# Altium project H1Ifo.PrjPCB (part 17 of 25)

## Sheet IfoEndX1.SchDoc: D1800185
size C; Engineer: Daniel Sigg; DocumentNumber: 5; Revision: 4; SheetNumber: 5; SheetTotal: 8
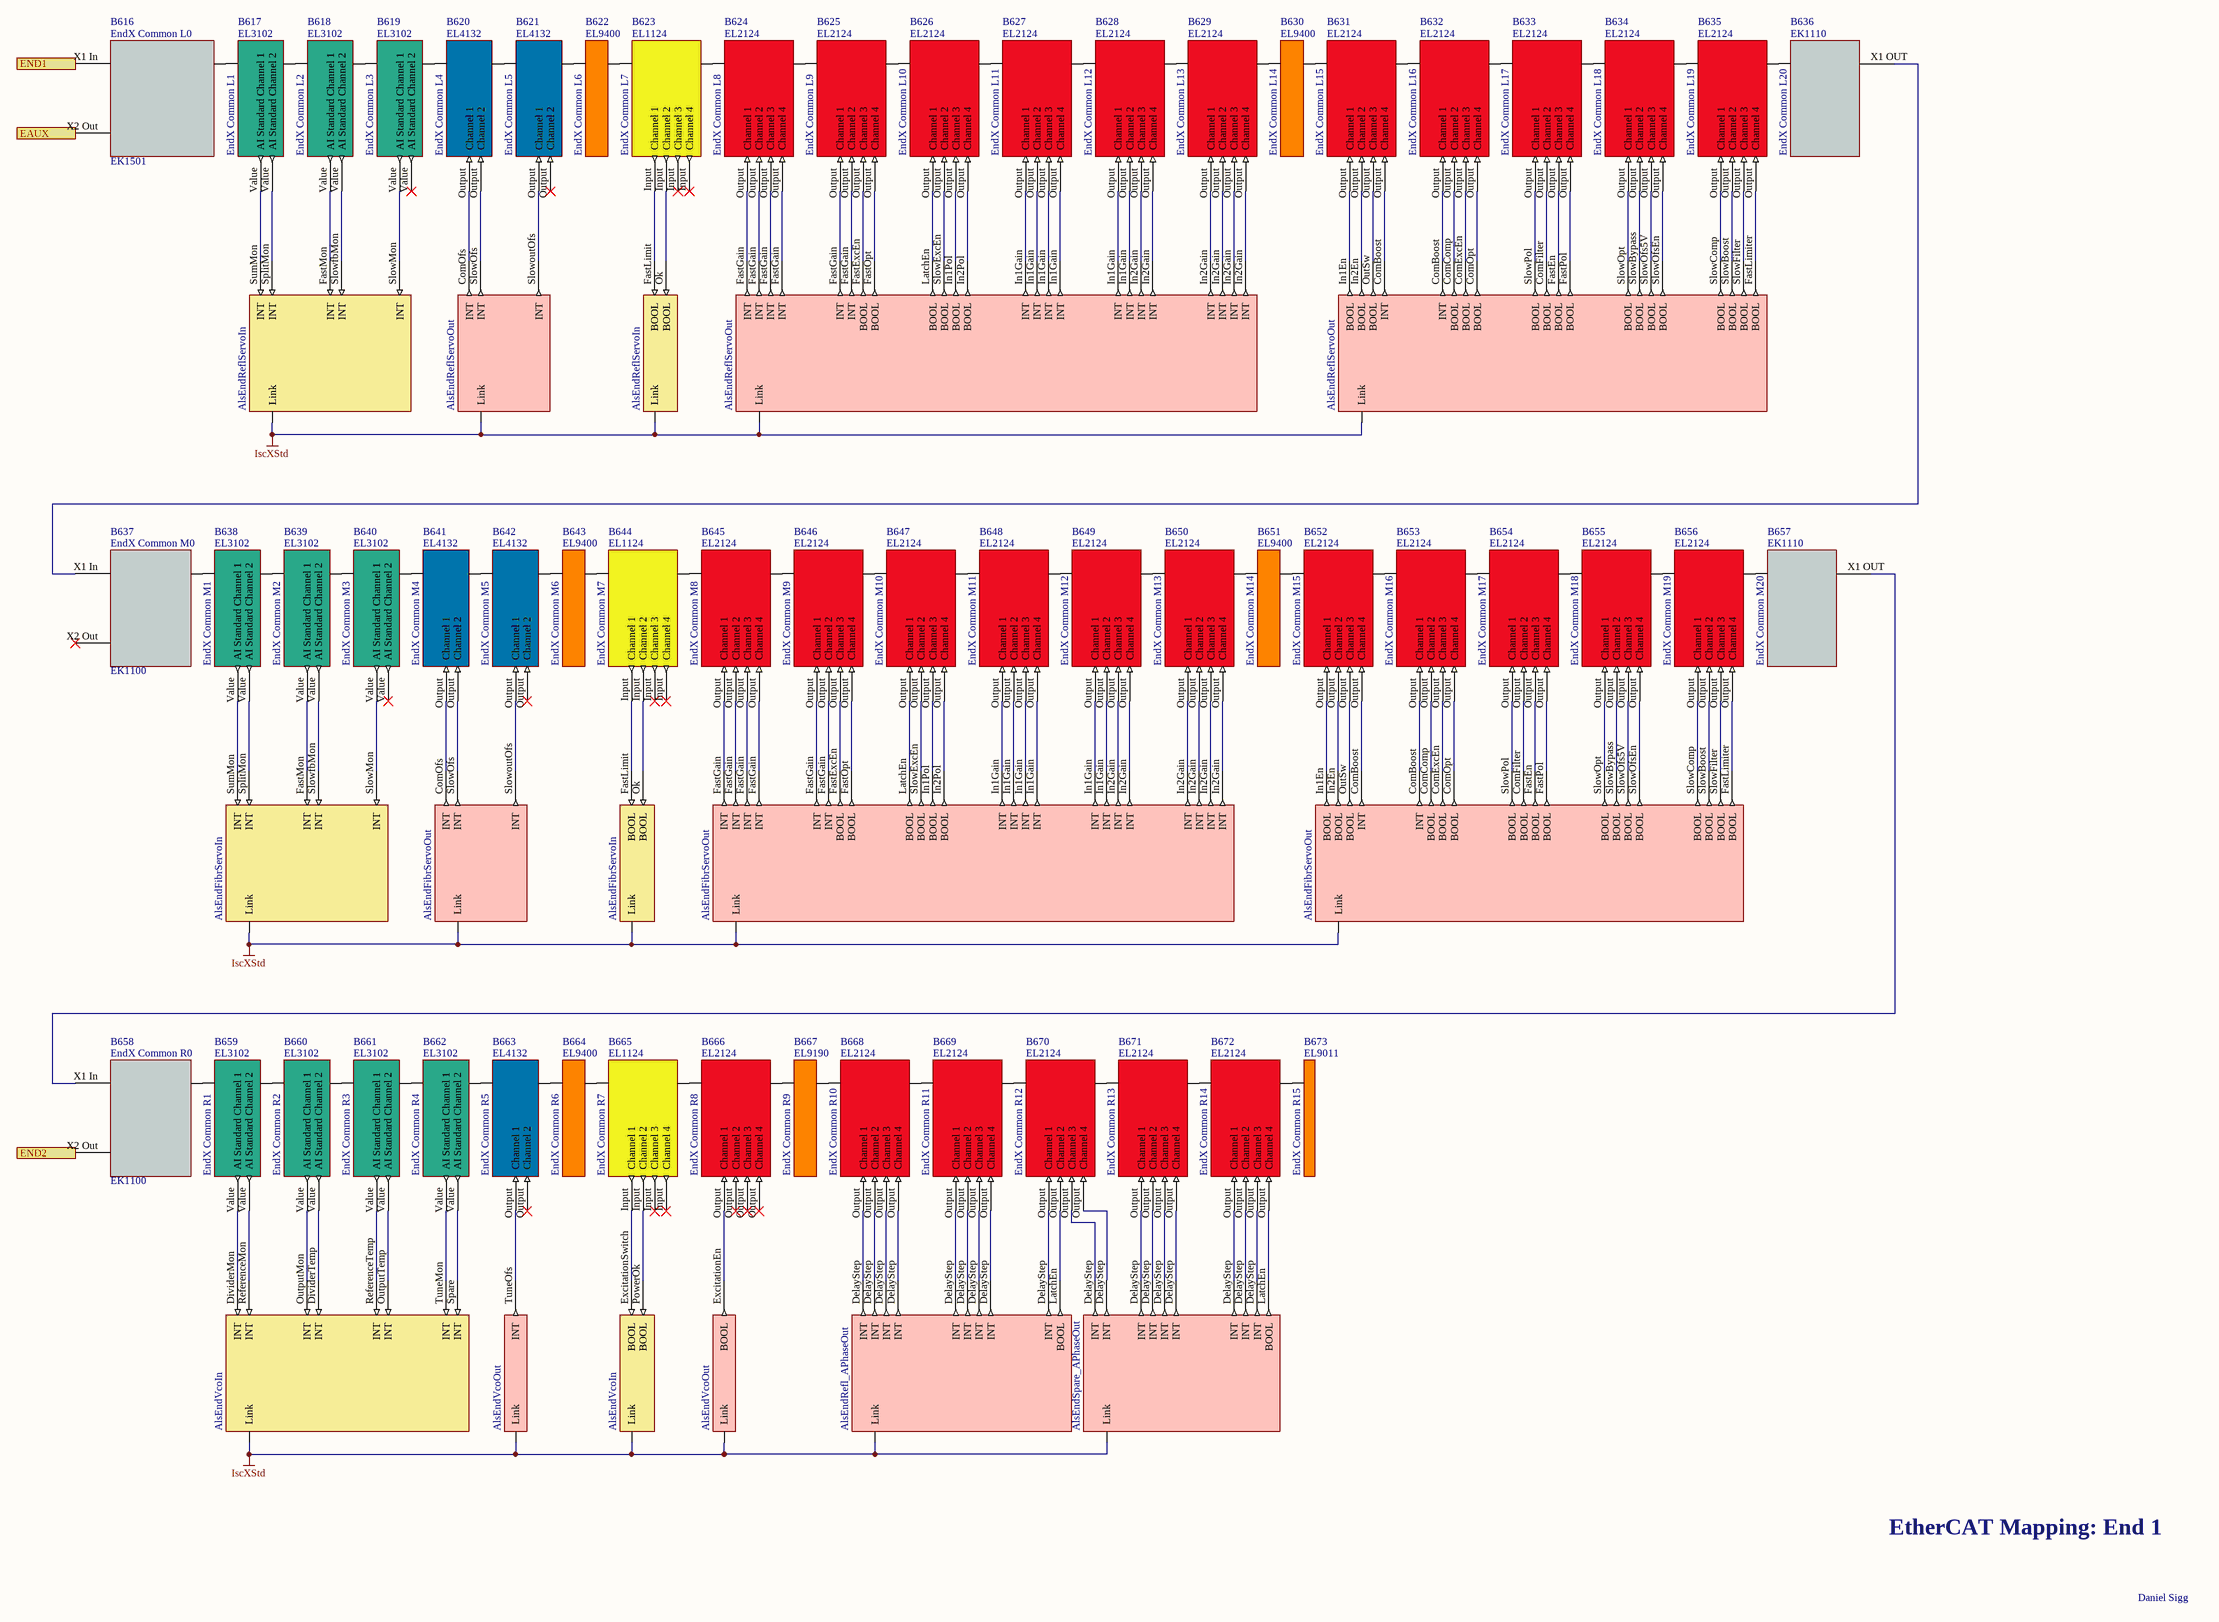
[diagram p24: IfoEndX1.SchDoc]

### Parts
B616  EndX Common L0  Part Number: EK1501  (mechanical)
B617  EndX Common L1  Part Number: EL3102  (mechanical)
B618  EndX Common L2  Part Number: EL3102  (mechanical)
B619  EndX Common L3  Part Number: EL3102  (mechanical)
B620  EndX Common L4  Part Number: EL4132  (mechanical)
B621  EndX Common L5  Part Number: EL4132  (mechanical)
B622  EndX Common L6  Part Number: EL9400  (mechanical)
B623  EndX Common L7  Part Number: EL1124  (mechanical)
B624  EndX Common L8  Part Number: EL2124  (mechanical)
B625  EndX Common L9  Part Number: EL2124  (mechanical)
B626  EndX Common L10  Part Number: EL2124  (mechanical)
B627  EndX Common L11  Part Number: EL2124  (mechanical)
B628  EndX Common L12  Part Number: EL2124  (mechanical)
B629  EndX Common L13  Part Number: EL2124  (mechanical)
B630  EndX Common L14  Part Number: EL9400  (mechanical)
B631  EndX Common L15  Part Number: EL2124  (mechanical)
B632  EndX Common L16  Part Number: EL2124  (mechanical)
B633  EndX Common L17  Part Number: EL2124  (mechanical)
B634  EndX Common L18  Part Number: EL2124  (mechanical)
B635  EndX Common L19  Part Number: EL2124  (mechanical)
B636  EndX Common L20  Part Number: EK1110  (mechanical)
B637  EndX Common M0  Part Number: EK1100  (mechanical)
B638  EndX Common M1  Part Number: EL3102  (mechanical)
B639  EndX Common M2  Part Number: EL3102  (mechanical)
B640  EndX Common M3  Part Number: EL3102  (mechanical)
B641  EndX Common M4  Part Number: EL4132  (mechanical)
B642  EndX Common M5  Part Number: EL4132  (mechanical)
B643  EndX Common M6  Part Number: EL9400  (mechanical)
B644  EndX Common M7  Part Number: EL1124  (mechanical)
B645  EndX Common M8  Part Number: EL2124  (mechanical)
B646  EndX Common M9  Part Number: EL2124  (mechanical)
B647  EndX Common M10  Part Number: EL2124  (mechanical)
B648  EndX Common M11  Part Number: EL2124  (mechanical)
B649  EndX Common M12  Part Number: EL2124  (mechanical)
B650  EndX Common M13  Part Number: EL2124  (mechanical)
B651  EndX Common M14  Part Number: EL9400  (mechanical)
B652  EndX Common M15  Part Number: EL2124  (mechanical)
B653  EndX Common M16  Part Number: EL2124  (mechanical)
B654  EndX Common M17  Part Number: EL2124  (mechanical)
B655  EndX Common M18  Part Number: EL2124  (mechanical)
B656  EndX Common M19  Part Number: EL2124  (mechanical)
B657  EndX Common M20  Part Number: EK1110  (mechanical)
B658  EndX Common R0  Part Number: EK1100  (mechanical)
B659  EndX Common R1  Part Number: EL3102  (mechanical)
B660  EndX Common R2  Part Number: EL3102  (mechanical)
B661  EndX Common R3  Part Number: EL3102  (mechanical)
B662  EndX Common R4  Part Number: EL3102  (mechanical)
B663  EndX Common R5  Part Number: EL4132  (mechanical)
B664  EndX Common R6  Part Number: EL9400  (mechanical)
B665  EndX Common R7  Part Number: EL1124  (mechanical)
B666  EndX Common R8  Part Number: EL2124  (mechanical)
B667  EndX Common R9  Part Number: EL9190  (mechanical)
B668  EndX Common R10  Part Number: EL2124  (mechanical)
B669  EndX Common R11  Part Number: EL2124  (mechanical)
B670  EndX Common R12  Part Number: EL2124  (mechanical)
B671  EndX Common R13  Part Number: EL2124  (mechanical)
B672  EndX Common R14  Part Number: EL2124  (mechanical)
B673  EndX Common R15  Part Number: EL9011  (mechanical)
V451  AlsEndVcoIn  (parts A,B of 2)  (no BOM)
V535  AlsEndReflServoIn  (parts A,B of 2)  (no BOM)
V536  AlsEndReflServoOut  (parts A,B,C of 3)  (no BOM)
V537  AlsEndFibrServoIn  (parts A,B of 2)  (no BOM)
V538  AlsEndFibrServoOut  (parts A,B,C of 3)  (no BOM)
V539  AlsEndVcoOut  (parts A,B of 2)  (no BOM)
V540  AlsEndRefl_APhaseOut  (no BOM)
V541  AlsEndSpare_APhaseOut  (no BOM)

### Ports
EAUX, END1, END2

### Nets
IscXStd: V451.0(Link) V451.1(Link) V535.1(Link) V535.?1(Link) V536.1(Link) V536.2(Link) V536.?1(Link) V537.1(Link) V537.?1(Link) V538.1(Link) V538.2(Link) V538.?1(Link) V539.0(Link) V539.1(Link) V540.?1(Link) V541.?1(Link)
NetB611_X1: B616.X1_In(A) ; port END1
NetB616_Ebus: B616.Ebus(B) B617.Ebus(A)
NetB616_X2 Out: B616.X2_Out(C) ; port EAUX
NetB617_Ebus: B617.Ebus(B) B618.Ebus(A)
NetB617_Value: B617.Value(AI_Standard_Channel_1) V535.SumMon(INT)
NetB617_Value: B617.Value(AI_Standard_Channel_2) V535.SplitMon(INT)  [a separate net that carries the same name]
NetB618_Ebus: B618.Ebus(B) B619.Ebus(A)
NetB618_Value: B618.Value(AI_Standard_Channel_1) V535.FastMon(INT)
NetB618_Value: B618.Value(AI_Standard_Channel_2) V535.SlowfbMon(INT)  [a separate net that carries the same name]
NetB619_Ebus: B619.Ebus(B) B620.Ebus(A)
NetB619_Value: B619.Value(AI_Standard_Channel_1) V535.SlowMon(INT)
NetB620_Ebus: B620.Ebus(B) B621.Ebus(A)
NetB620_Output: B620.Output(Channel_1) V536.ComOfs(INT)
NetB620_Output: B620.Output(Channel_2) V536.SlowOfs(INT)  [a separate net that carries the same name]
NetB621_Ebus: B621.Ebus(B) B622.Ebus(A)
NetB621_Output: B621.Output(Channel_1) V536.SlowoutOfs(INT)
NetB622_Ebus: B622.Ebus(B) B623.Ebus(A)
NetB623_Ebus: B623.Ebus(B) B624.Ebus(A)
NetB623_Input: B623.Input(Channel_1) V535.FastLimit(BOOL)
NetB623_Input: B623.Input(Channel_2) V535.Ok(BOOL)  [a separate net that carries the same name]
NetB624_Ebus: B624.Ebus(B) B625.Ebus(A)
NetB624_Output: B624.Output(Channel_1) V536.FastGain(INT)
NetB624_Output: B624.Output(Channel_2) V536.FastGain(INT)  [a separate net that carries the same name]
NetB624_Output: B624.Output(Channel_3) V536.FastGain(INT)  [a separate net that carries the same name]
NetB624_Output: B624.Output(Channel_4) V536.FastGain(INT)  [a separate net that carries the same name]
NetB625_Ebus: B625.Ebus(B) B626.Ebus(A)
NetB625_Output: B625.Output(Channel_1) V536.FastGain(INT)
NetB625_Output: B625.Output(Channel_2) V536.FastGain(INT)  [a separate net that carries the same name]
NetB625_Output: B625.Output(Channel_3) V536.FastExcEn(BOOL)  [a separate net that carries the same name]
NetB625_Output: B625.Output(Channel_4) V536.FastOpt(BOOL)  [a separate net that carries the same name]
NetB626_Ebus: B626.Ebus(B) B627.Ebus(A)
NetB626_Output: B626.Output(Channel_1) V536.LatchEn(BOOL)
NetB626_Output: B626.Output(Channel_2) V536.SlowExcEn(BOOL)  [a separate net that carries the same name]
NetB626_Output: B626.Output(Channel_3) V536.In1Pol(BOOL)  [a separate net that carries the same name]
NetB626_Output: B626.Output(Channel_4) V536.In2Pol(BOOL)  [a separate net that carries the same name]
NetB627_Ebus: B627.Ebus(B) B628.Ebus(A)
NetB627_Output: B627.Output(Channel_1) V536.In1Gain(INT)
NetB627_Output: B627.Output(Channel_2) V536.In1Gain(INT)  [a separate net that carries the same name]
NetB627_Output: B627.Output(Channel_3) V536.In1Gain(INT)  [a separate net that carries the same name]
NetB627_Output: B627.Output(Channel_4) V536.In1Gain(INT)  [a separate net that carries the same name]
NetB628_Ebus: B628.Ebus(B) B629.Ebus(A)
NetB628_Output: B628.Output(Channel_1) V536.In1Gain(INT)
NetB628_Output: B628.Output(Channel_2) V536.In1Gain(INT)  [a separate net that carries the same name]
NetB628_Output: B628.Output(Channel_3) V536.In2Gain(INT)  [a separate net that carries the same name]
NetB628_Output: B628.Output(Channel_4) V536.In2Gain(INT)  [a separate net that carries the same name]
NetB629_Ebus: B629.Ebus(B) B630.Ebus(A)
NetB629_Output: B629.Output(Channel_1) V536.In2Gain(INT)
NetB629_Output: B629.Output(Channel_2) V536.In2Gain(INT)  [a separate net that carries the same name]
NetB629_Output: B629.Output(Channel_3) V536.In2Gain(INT)  [a separate net that carries the same name]
NetB629_Output: B629.Output(Channel_4) V536.In2Gain(INT)  [a separate net that carries the same name]
NetB630_Ebus: B630.Ebus(B) B631.Ebus(A)
NetB631_Ebus: B631.Ebus(B) B632.Ebus(A)
NetB631_Output: B631.Output(Channel_1) V536.In1En(BOOL)
NetB631_Output: B631.Output(Channel_2) V536.In2En(BOOL)  [a separate net that carries the same name]
NetB631_Output: B631.Output(Channel_3) V536.OutSw(BOOL)  [a separate net that carries the same name]
NetB631_Output: B631.Output(Channel_4) V536.ComBoost(INT)  [a separate net that carries the same name]
NetB632_Ebus: B632.Ebus(B) B633.Ebus(A)
NetB632_Output: B632.Output(Channel_1) V536.ComBoost(INT)
NetB632_Output: B632.Output(Channel_2) V536.ComComp(BOOL)  [a separate net that carries the same name]
NetB632_Output: B632.Output(Channel_3) V536.ComExcEn(BOOL)  [a separate net that carries the same name]
NetB632_Output: B632.Output(Channel_4) V536.ComOpt(BOOL)  [a separate net that carries the same name]
NetB633_Ebus: B633.Ebus(B) B634.Ebus(A)
NetB633_Output: B633.Output(Channel_1) V536.SlowPol(BOOL)
NetB633_Output: B633.Output(Channel_2) V536.ComFilter(BOOL)  [a separate net that carries the same name]
NetB633_Output: B633.Output(Channel_3) V536.FastEn(BOOL)  [a separate net that carries the same name]
NetB633_Output: B633.Output(Channel_4) V536.FastPol(BOOL)  [a separate net that carries the same name]
NetB634_Ebus: B634.Ebus(B) B635.Ebus(A)
NetB634_Output: B634.Output(Channel_1) V536.SlowOpt(BOOL)
NetB634_Output: B634.Output(Channel_2) V536.SlowBypass(BOOL)  [a separate net that carries the same name]
NetB634_Output: B634.Output(Channel_3) V536.SlowOfs5V(BOOL)  [a separate net that carries the same name]
NetB634_Output: B634.Output(Channel_4) V536.SlowOfsEn(BOOL)  [a separate net that carries the same name]
NetB635_Ebus: B635.Ebus(B) B636.Ebus(A)
NetB635_Output: B635.Output(Channel_1) V536.SlowComp(BOOL)
NetB635_Output: B635.Output(Channel_2) V536.SlowBoost(BOOL)  [a separate net that carries the same name]
NetB635_Output: B635.Output(Channel_3) V536.SlowFilter(BOOL)  [a separate net that carries the same name]
NetB635_Output: B635.Output(Channel_4) V536.FastLimiter(BOOL)  [a separate net that carries the same name]
NetB636_X1 OUT: B636.X1_OUT(B) B637.X1_In(A)
NetB637_Ebus: B637.Ebus(B) B638.Ebus(A)
NetB638_Ebus: B638.Ebus(B) B639.Ebus(A)
NetB638_Value: B638.Value(AI_Standard_Channel_1) V537.SumMon(INT)
NetB638_Value: B638.Value(AI_Standard_Channel_2) V537.SplitMon(INT)  [a separate net that carries the same name]
NetB639_Ebus: B639.Ebus(B) B640.Ebus(A)
NetB639_Value: B639.Value(AI_Standard_Channel_1) V537.FastMon(INT)
NetB639_Value: B639.Value(AI_Standard_Channel_2) V537.SlowfbMon(INT)  [a separate net that carries the same name]
NetB640_Ebus: B640.Ebus(B) B641.Ebus(A)
NetB640_Value: B640.Value(AI_Standard_Channel_1) V537.SlowMon(INT)
NetB641_Ebus: B641.Ebus(B) B642.Ebus(A)
NetB641_Output: B641.Output(Channel_1) V538.ComOfs(INT)
NetB641_Output: B641.Output(Channel_2) V538.SlowOfs(INT)  [a separate net that carries the same name]
NetB642_Ebus: B642.Ebus(B) B643.Ebus(A)
NetB642_Output: B642.Output(Channel_1) V538.SlowoutOfs(INT)
NetB643_Ebus: B643.Ebus(B) B644.Ebus(A)
NetB644_Ebus: B644.Ebus(B) B645.Ebus(A)
NetB644_Input: B644.Input(Channel_1) V537.FastLimit(BOOL)
NetB644_Input: B644.Input(Channel_2) V537.Ok(BOOL)  [a separate net that carries the same name]
NetB645_Ebus: B645.Ebus(B) B646.Ebus(A)
NetB645_Output: B645.Output(Channel_1) V538.FastGain(INT)
NetB645_Output: B645.Output(Channel_2) V538.FastGain(INT)  [a separate net that carries the same name]
NetB645_Output: B645.Output(Channel_3) V538.FastGain(INT)  [a separate net that carries the same name]
NetB645_Output: B645.Output(Channel_4) V538.FastGain(INT)  [a separate net that carries the same name]
NetB646_Ebus: B646.Ebus(B) B647.Ebus(A)
NetB646_Output: B646.Output(Channel_1) V538.FastGain(INT)
NetB646_Output: B646.Output(Channel_2) V538.FastGain(INT)  [a separate net that carries the same name]
NetB646_Output: B646.Output(Channel_3) V538.FastExcEn(BOOL)  [a separate net that carries the same name]
NetB646_Output: B646.Output(Channel_4) V538.FastOpt(BOOL)  [a separate net that carries the same name]
NetB647_Ebus: B647.Ebus(B) B648.Ebus(A)
NetB647_Output: B647.Output(Channel_1) V538.LatchEn(BOOL)
NetB647_Output: B647.Output(Channel_2) V538.SlowExcEn(BOOL)  [a separate net that carries the same name]
NetB647_Output: B647.Output(Channel_3) V538.In1Pol(BOOL)  [a separate net that carries the same name]
NetB647_Output: B647.Output(Channel_4) V538.In2Pol(BOOL)  [a separate net that carries the same name]
NetB648_Ebus: B648.Ebus(B) B649.Ebus(A)
NetB648_Output: B648.Output(Channel_1) V538.In1Gain(INT)
NetB648_Output: B648.Output(Channel_2) V538.In1Gain(INT)  [a separate net that carries the same name]
NetB648_Output: B648.Output(Channel_3) V538.In1Gain(INT)  [a separate net that carries the same name]
NetB648_Output: B648.Output(Channel_4) V538.In1Gain(INT)  [a separate net that carries the same name]
NetB649_Ebus: B649.Ebus(B) B650.Ebus(A)
NetB649_Output: B649.Output(Channel_1) V538.In1Gain(INT)
NetB649_Output: B649.Output(Channel_2) V538.In1Gain(INT)  [a separate net that carries the same name]
NetB649_Output: B649.Output(Channel_3) V538.In2Gain(INT)  [a separate net that carries the same name]
NetB649_Output: B649.Output(Channel_4) V538.In2Gain(INT)  [a separate net that carries the same name]
NetB650_Ebus: B650.Ebus(B) B651.Ebus(A)
NetB650_Output: B650.Output(Channel_1) V538.In2Gain(INT)
NetB650_Output: B650.Output(Channel_2) V538.In2Gain(INT)  [a separate net that carries the same name]
NetB650_Output: B650.Output(Channel_3) V538.In2Gain(INT)  [a separate net that carries the same name]
NetB650_Output: B650.Output(Channel_4) V538.In2Gain(INT)  [a separate net that carries the same name]
NetB651_Ebus: B651.Ebus(B) B652.Ebus(A)
NetB652_Ebus: B652.Ebus(B) B653.Ebus(A)
NetB652_Output: B652.Output(Channel_1) V538.In1En(BOOL)
NetB652_Output: B652.Output(Channel_2) V538.In2En(BOOL)  [a separate net that carries the same name]
NetB652_Output: B652.Output(Channel_3) V538.OutSw(BOOL)  [a separate net that carries the same name]
NetB652_Output: B652.Output(Channel_4) V538.ComBoost(INT)  [a separate net that carries the same name]
NetB653_Ebus: B653.Ebus(B) B654.Ebus(A)
NetB653_Output: B653.Output(Channel_1) V538.ComBoost(INT)
NetB653_Output: B653.Output(Channel_2) V538.ComComp(BOOL)  [a separate net that carries the same name]
NetB653_Output: B653.Output(Channel_3) V538.ComExcEn(BOOL)  [a separate net that carries the same name]
NetB653_Output: B653.Output(Channel_4) V538.ComOpt(BOOL)  [a separate net that carries the same name]
NetB654_Ebus: B654.Ebus(B) B655.Ebus(A)
NetB654_Output: B654.Output(Channel_1) V538.SlowPol(BOOL)
NetB654_Output: B654.Output(Channel_2) V538.ComFilter(BOOL)  [a separate net that carries the same name]
NetB654_Output: B654.Output(Channel_3) V538.FastEn(BOOL)  [a separate net that carries the same name]
NetB654_Output: B654.Output(Channel_4) V538.FastPol(BOOL)  [a separate net that carries the same name]
NetB655_Ebus: B655.Ebus(B) B656.Ebus(A)
NetB655_Output: B655.Output(Channel_1) V538.SlowOpt(BOOL)
NetB655_Output: B655.Output(Channel_2) V538.SlowBypass(BOOL)  [a separate net that carries the same name]
NetB655_Output: B655.Output(Channel_3) V538.SlowOfs5V(BOOL)  [a separate net that carries the same name]
NetB655_Output: B655.Output(Channel_4) V538.SlowOfsEn(BOOL)  [a separate net that carries the same name]
NetB656_Ebus: B656.Ebus(B) B657.Ebus(A)
NetB656_Output: B656.Output(Channel_1) V538.SlowComp(BOOL)
NetB656_Output: B656.Output(Channel_2) V538.SlowBoost(BOOL)  [a separate net that carries the same name]
NetB656_Output: B656.Output(Channel_3) V538.SlowFilter(BOOL)  [a separate net that carries the same name]
NetB656_Output: B656.Output(Channel_4) V538.FastLimiter(BOOL)  [a separate net that carries the same name]
NetB657_X1 OUT: B657.X1_OUT(B) B658.X1_In(A)
NetB658_Ebus: B658.Ebus(B) B659.Ebus(A)
NetB658_X2 Out: B658.X2_Out(C) ; port END2
NetB659_Ebus: B659.Ebus(B) B660.Ebus(A)
NetB659_Value: B659.Value(AI_Standard_Channel_1) V451.DividerMon(INT)
NetB659_Value: B659.Value(AI_Standard_Channel_2) V451.ReferenceMon(INT)  [a separate net that carries the same name]
NetB660_Ebus: B660.Ebus(B) B661.Ebus(A)
NetB660_Value: B660.Value(AI_Standard_Channel_1) V451.OutputMon(INT)
NetB660_Value: B660.Value(AI_Standard_Channel_2) V451.DividerTemp(INT)  [a separate net that carries the same name]
NetB661_Ebus: B661.Ebus(B) B662.Ebus(A)
NetB661_Value: B661.Value(AI_Standard_Channel_1) V451.ReferenceTemp(INT)
NetB661_Value: B661.Value(AI_Standard_Channel_2) V451.OutputTemp(INT)  [a separate net that carries the same name]
NetB662_Ebus: B662.Ebus(B) B663.Ebus(A)
NetB662_Value: B662.Value(AI_Standard_Channel_1) V451.TuneMon(INT)
NetB662_Value: B662.Value(AI_Standard_Channel_2) V451.Spare(INT)  [a separate net that carries the same name]
NetB663_Ebus: B663.Ebus(B) B664.Ebus(A)
NetB663_Output: B663.Output(Channel_1) V539.TuneOfs(INT)
NetB664_Ebus: B664.Ebus(B) B665.Ebus(A)
NetB665_Ebus: B665.Ebus(B) B666.Ebus(A)
NetB665_Input: B665.Input(Channel_1) V451.ExcitationSwitch(BOOL)
NetB665_Input: B665.Input(Channel_2) V451.PowerOk(BOOL)  [a separate net that carries the same name]
NetB666_Ebus: B666.Ebus(B) B667.Ebus(A)
NetB666_Output: B666.Output(Channel_1) V539.ExcitationEn(BOOL)
NetB667_Ebus: B667.Ebus(B) B668.Ebus(A)
NetB668_Ebus: B668.Ebus(B) B669.Ebus(A)
NetB668_Output: B668.Output(Channel_1) V540.DelayStep(INT)
NetB668_Output: B668.Output(Channel_2) V540.DelayStep(INT)  [a separate net that carries the same name]
NetB668_Output: B668.Output(Channel_3) V540.DelayStep(INT)  [a separate net that carries the same name]
NetB668_Output: B668.Output(Channel_4) V540.DelayStep(INT)  [a separate net that carries the same name]
NetB669_Ebus: B669.Ebus(B) B670.Ebus(A)
NetB669_Output: B669.Output(Channel_1) V540.DelayStep(INT)
NetB669_Output: B669.Output(Channel_2) V540.DelayStep(INT)  [a separate net that carries the same name]
NetB669_Output: B669.Output(Channel_3) V540.DelayStep(INT)  [a separate net that carries the same name]
NetB669_Output: B669.Output(Channel_4) V540.DelayStep(INT)  [a separate net that carries the same name]
NetB670_Ebus: B670.Ebus(B) B671.Ebus(A)
NetB670_Output: B670.Output(Channel_1) V540.DelayStep(INT)
NetB670_Output: B670.Output(Channel_2) V540.LatchEn(BOOL)  [a separate net that carries the same name]
NetB670_Output: B670.Output(Channel_3) V541.DelayStep(INT)  [a separate net that carries the same name]
NetB670_Output: B670.Output(Channel_4) V541.DelayStep(INT)  [a separate net that carries the same name]
NetB671_Ebus: B671.Ebus(B) B672.Ebus(A)
NetB671_Output: B671.Output(Channel_1) V541.DelayStep(INT)
NetB671_Output: B671.Output(Channel_2) V541.DelayStep(INT)  [a separate net that carries the same name]
NetB671_Output: B671.Output(Channel_3) V541.DelayStep(INT)  [a separate net that carries the same name]
NetB671_Output: B671.Output(Channel_4) V541.DelayStep(INT)  [a separate net that carries the same name]
NetB672_Ebus: B672.Ebus(B) B673.Ebus(A)
NetB672_Output: B672.Output(Channel_1) V541.DelayStep(INT)
NetB672_Output: B672.Output(Channel_2) V541.DelayStep(INT)  [a separate net that carries the same name]
NetB672_Output: B672.Output(Channel_3) V541.DelayStep(INT)  [a separate net that carries the same name]
NetB672_Output: B672.Output(Channel_4) V541.LatchEn(BOOL)  [a separate net that carries the same name]

Not connected (* = marked no-connect by the designer): B637 X2 Out(C)*

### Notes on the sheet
- EtherCAT Mapping: End 1
- Daniel Sigg

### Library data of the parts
B616 = CouplerEK1501: Fiber Coupler; Rail: Left; BoxNextB: ALWNPSLP; BoxNextC: EQPTNBUH; BoxPrev: QCEWWLIP; PortPrevFull: 1006/D; PortPrevShort: D 'X1'; Fullname: TIID^End X (EtherCAT)^EndX Link L0 (EK1501-0010)^EndX Link L6 (EK1521)^EndX Common L0 (EK1501); BoxPorts: Junction; BoxAddr: 1007; Disabled: False
B617 = TerminalEL3102: EtherCAT Terminal EL3102 2-chn Analog Input; Rail: Left; BoxNextB: EBQCPTUD; BoxPrev: QEYXEFKI; PortPrevFull: 1007/B; PortPrevShort: B; Fullname: TIID^End X (EtherCAT)^EndX Link L0 (EK1501-0010)^EndX Link L6 (EK1521)^EndX Common L0 (EK1501)^EndX Common L1 (EL3102); BoxAddr: 1008; Disabled: False
B618 = TerminalEL3102: EtherCAT Terminal EL3102 2-chn Analog Input; Rail: Left; BoxNextB: FEGLKUHE; BoxPrev: ALWNPSLP; PortPrevFull: 1008/B; PortPrevShort: B; Fullname: TIID^End X (EtherCAT)^EndX Link L0 (EK1501-0010)^EndX Link L6 (EK1521)^EndX Common L0 (EK1501)^EndX Common L2 (EL3102); BoxAddr: 1009; Disabled: False
B619 = TerminalEL3102: EtherCAT Terminal EL3102 2-chn Analog Input; Rail: Left; BoxNextB: KEQMGXGO; BoxPrev: EBQCPTUD; PortPrevFull: 1009/B; PortPrevShort: B; Fullname: TIID^End X (EtherCAT)^EndX Link L0 (EK1501-0010)^EndX Link L6 (EK1521)^EndX Common L0 (EK1501)^EndX Common L3 (EL3102); BoxAddr: 1010; Disabled: False
B620 = TerminalEL4132: EtherCAT Terminal EL4132 2-chn Analog Ouput; Rail: Left; BoxNextB: UJWUAITM; BoxPrev: FEGLKUHE; PortPrevFull: 1010/B; PortPrevShort: B; Fullname: TIID^End X (EtherCAT)^EndX Link L0 (EK1501-0010)^EndX Link L6 (EK1521)^EndX Common L0 (EK1501)^EndX Common L4 (EL4132); BoxAddr: 1011; Disabled: False
B621 = TerminalEL4132: EtherCAT Terminal EL4132 2-chn Analog Ouput; Rail: Left; BoxNextB: BWQPTTRB; BoxPrev: KEQMGXGO; PortPrevFull: 1011/B; PortPrevShort: B; Fullname: TIID^End X (EtherCAT)^EndX Link L0 (EK1501-0010)^EndX Link L6 (EK1521)^EndX Common L0 (EK1501)^EndX Common L5 (EL4132); BoxAddr: 1012; Disabled: False
B622 = TerminalEL9400: EtherCAT Terminal EL9400 Power; BoxType: TerminalPassive; Rail: Left; BoxNextB: XDGUWXPP; BoxPrev: UJWUAITM; PortPrevShort: B; Fullname: TIID^End X (EtherCAT)^EndX Link L0 (EK1501-0010)^EndX Link L6 (EK1521)^EndX Common L0 (EK1501)^EndX Common L6 (EL9400); Disabled: False
B623 = TerminalEL1124: EtherCAT Terminal EL1124 4-chn Digital Input; Rail: Left; BoxNextB: NJHQNGJX; BoxPrev: BWQPTTRB; PortPrevFull: 1012/B; PortPrevShort: B; Fullname: TIID^End X (EtherCAT)^EndX Link L0 (EK1501-0010)^EndX Link L6 (EK1521)^EndX Common L0 (EK1501)^EndX Common L7 (EL1124); BoxAddr: 1013; Disabled: False
B624 = TerminalEL2124: EtherCAT Terminal EL2124 4-chn Digital Ouput; Rail: Left; BoxNextB: TRYOWWYG; BoxPrev: XDGUWXPP; PortPrevFull: 1013/B; PortPrevShort: B; Fullname: TIID^End X (EtherCAT)^EndX Link L0 (EK1501-0010)^EndX Link L6 (EK1521)^EndX Common L0 (EK1501)^EndX Common L8 (EL2124); BoxAddr: 1014; Disabled: False
B625 = TerminalEL2124: EtherCAT Terminal EL2124 4-chn Digital Ouput; Rail: Left; BoxNextB: PCTGBJAY; BoxPrev: NJHQNGJX; PortPrevFull: 1014/B; PortPrevShort: B; Fullname: TIID^End X (EtherCAT)^EndX Link L0 (EK1501-0010)^EndX Link L6 (EK1521)^EndX Common L0 (EK1501)^EndX Common L9 (EL2124); BoxAddr: 1015; Disabled: False
B626 = TerminalEL2124: EtherCAT Terminal EL2124 4-chn Digital Ouput; Rail: Left; BoxNextB: XJVCXBDL; BoxPrev: TRYOWWYG; PortPrevFull: 1015/B; PortPrevShort: B; Fullname: TIID^End X (EtherCAT)^EndX Link L0 (EK1501-0010)^EndX Link L6 (EK1521)^EndX Common L0 (EK1501)^EndX Common L10 (EL2124); BoxAddr: 1016; Disabled: False
B627 = TerminalEL2124: EtherCAT Terminal EL2124 4-chn Digital Ouput; Rail: Left; BoxNextB: QSXDOKJD; BoxPrev: PCTGBJAY; PortPrevFull: 1016/B; PortPrevShort: B; Fullname: TIID^End X (EtherCAT)^EndX Link L0 (EK1501-0010)^EndX Link L6 (EK1521)^EndX Common L0 (EK1501)^EndX Common L11 (EL2124); BoxAddr: 1017; Disabled: False
B628 = TerminalEL2124: EtherCAT Terminal EL2124 4-chn Digital Ouput; Rail: Left; BoxNextB: VCTWFDRF; BoxPrev: XJVCXBDL; PortPrevFull: 1017/B; PortPrevShort: B; Fullname: TIID^End X (EtherCAT)^EndX Link L0 (EK1501-0010)^EndX Link L6 (EK1521)^EndX Common L0 (EK1501)^EndX Common L12 (EL2124); BoxAddr: 1018; Disabled: False
B629 = TerminalEL2124: EtherCAT Terminal EL2124 4-chn Digital Ouput; Rail: Left; BoxNextB: CMFWLBMH; BoxPrev: QSXDOKJD; PortPrevFull: 1018/B; PortPrevShort: B; Fullname: TIID^End X (EtherCAT)^EndX Link L0 (EK1501-0010)^EndX Link L6 (EK1521)^EndX Common L0 (EK1501)^EndX Common L13 (EL2124); BoxAddr: 1019; Disabled: False
B630 = TerminalEL9400: EtherCAT Terminal EL9400 Power; BoxType: TerminalPassive; Rail: Left; BoxNextB: KERMTVIK; BoxPrev: VCTWFDRF; PortPrevShort: B; Fullname: TIID^End X (EtherCAT)^EndX Link L0 (EK1501-0010)^EndX Link L6 (EK1521)^EndX Common L0 (EK1501)^EndX Common L14 (EL9400); Disabled: False
B631 = TerminalEL2124: EtherCAT Terminal EL2124 4-chn Digital Ouput; Rail: Left; BoxNextB: YINPNONS; BoxPrev: CMFWLBMH; PortPrevFull: 1019/B; PortPrevShort: B; Fullname: TIID^End X (EtherCAT)^EndX Link L0 (EK1501-0010)^EndX Link L6 (EK1521)^EndX Common L0 (EK1501)^EndX Common L15 (EL2124); BoxAddr: 1020; Disabled: False
B632 = TerminalEL2124: EtherCAT Terminal EL2124 4-chn Digital Ouput; Rail: Left; BoxNextB: EWLKUDWD; BoxPrev: KERMTVIK; PortPrevFull: 1020/B; PortPrevShort: B; Fullname: TIID^End X (EtherCAT)^EndX Link L0 (EK1501-0010)^EndX Link L6 (EK1521)^EndX Common L0 (EK1501)^EndX Common L16 (EL2124); BoxAddr: 1021; Disabled: False
B633 = TerminalEL2124: EtherCAT Terminal EL2124 4-chn Digital Ouput; Rail: Left; BoxNextB: HAFPOEPE; BoxPrev: YINPNONS; PortPrevFull: 1021/B; PortPrevShort: B; Fullname: TIID^End X (EtherCAT)^EndX Link L0 (EK1501-0010)^EndX Link L6 (EK1521)^EndX Common L0 (EK1501)^EndX Common L17 (EL2124); BoxAddr: 1022; Disabled: False
B634 = TerminalEL2124: EtherCAT Terminal EL2124 4-chn Digital Ouput; Rail: Left; BoxNextB: VLXQJIDQ; BoxPrev: EWLKUDWD; PortPrevFull: 1022/B; PortPrevShort: B; Fullname: TIID^End X (EtherCAT)^EndX Link L0 (EK1501-0010)^EndX Link L6 (EK1521)^EndX Common L0 (EK1501)^EndX Common L18 (EL2124); BoxAddr: 1023; Disabled: False
B635 = TerminalEL2124: EtherCAT Terminal EL2124 4-chn Digital Ouput; Rail: Left; BoxNextB: LMAYUXYC; BoxPrev: HAFPOEPE; PortPrevFull: 1023/B; PortPrevShort: B; Fullname: TIID^End X (EtherCAT)^EndX Link L0 (EK1501-0010)^EndX Link L6 (EK1521)^EndX Common L0 (EK1501)^EndX Common L19 (EL2124); BoxAddr: 1024; Disabled: False
B636 = CouplerEK1110: EtherCAT Coupler Extension; BoxType: Terminal; Rail: Left; BoxNextB: PHJMDTBT; BoxPrev: VLXQJIDQ; PortPrevFull: 1024/B; PortPrevShort: B; Fullname: TIID^End X (EtherCAT)^EndX Link L0 (EK1501-0010)^EndX Link L6 (EK1521)^EndX Common L0 (EK1501)^EndX Common L20 (EK1110); BoxAddr: 1025; Disabled: False
B637 = CouplerEK1100: EtherCAT Coupler; Rail: Middle; BoxNextB: XESLLLVY; BoxPrev: LMAYUXYC; PortPrevFull: 1025/B; PortPrevShort: B 'X1 OUT'; Fullname: TIID^End X (EtherCAT)^EndX Link L0 (EK1501-0010)^EndX Link L6 (EK1521)^EndX Common M0 (EK1100); BoxPorts: Junction; BoxAddr: 1026; Disabled: False
B638 = TerminalEL3102: EtherCAT Terminal EL3102 2-chn Analog Input; Rail: Middle; BoxNextB: QVYLGDQR; BoxPrev: PHJMDTBT; PortPrevFull: 1026/B; PortPrevShort: B; Fullname: TIID^End X (EtherCAT)^EndX Link L0 (EK1501-0010)^EndX Link L6 (EK1521)^EndX Common M0 (EK1100)^EndX Common M1 (EL3102); BoxAddr: 1027; Disabled: False
B639 = TerminalEL3102: EtherCAT Terminal EL3102 2-chn Analog Input; Rail: Middle; BoxNextB: UVHYRDPO; BoxPrev: XESLLLVY; PortPrevFull: 1027/B; PortPrevShort: B; Fullname: TIID^End X (EtherCAT)^EndX Link L0 (EK1501-0010)^EndX Link L6 (EK1521)^EndX Common M0 (EK1100)^EndX Common M2 (EL3102); BoxAddr: 1028; Disabled: False
B640 = TerminalEL3102: EtherCAT Terminal EL3102 2-chn Analog Input; Rail: Middle; BoxNextB: NTLBGNOL; BoxPrev: QVYLGDQR; PortPrevFull: 1028/B; PortPrevShort: B; Fullname: TIID^End X (EtherCAT)^EndX Link L0 (EK1501-0010)^EndX Link L6 (EK1521)^EndX Common M0 (EK1100)^EndX Common M3 (EL3102); BoxAddr: 1029; Disabled: False
B641 = TerminalEL4132: EtherCAT Terminal EL4132 2-chn Analog Ouput; Rail: Middle; BoxNextB: NSSWSDAC; BoxPrev: UVHYRDPO; PortPrevFull: 1029/B; PortPrevShort: B; Fullname: TIID^End X (EtherCAT)^EndX Link L0 (EK1501-0010)^EndX Link L6 (EK1521)^EndX Common M0 (EK1100)^EndX Common M4 (EL4132); BoxAddr: 1030; Disabled: False
B642 = TerminalEL4132: EtherCAT Terminal EL4132 2-chn Analog Ouput; Rail: Middle; BoxNextB: HKVRUHNS; BoxPrev: NTLBGNOL; PortPrevFull: 1030/B; PortPrevShort: B; Fullname: TIID^End X (EtherCAT)^EndX Link L0 (EK1501-0010)^EndX Link L6 (EK1521)^EndX Common M0 (EK1100)^EndX Common M5 (EL4132); BoxAddr: 1031; Disabled: False
B643 = TerminalEL9400: EtherCAT Terminal EL9400 Power; BoxType: TerminalPassive; Rail: Middle; BoxNextB: XUXHOGEX; BoxPrev: NSSWSDAC; PortPrevShort: B; Fullname: TIID^End X (EtherCAT)^EndX Link L0 (EK1501-0010)^EndX Link L6 (EK1521)^EndX Common M0 (EK1100)^EndX Common M6 (EL9400); Disabled: False
B644 = TerminalEL1124: EtherCAT Terminal EL1124 4-chn Digital Input; Rail: Middle; BoxNextB: KVUVDLYS; BoxPrev: HKVRUHNS; PortPrevFull: 1031/B; PortPrevShort: B; Fullname: TIID^End X (EtherCAT)^EndX Link L0 (EK1501-0010)^EndX Link L6 (EK1521)^EndX Common M0 (EK1100)^EndX Common M7 (EL1124); BoxAddr: 1032; Disabled: False
B645 = TerminalEL2124: EtherCAT Terminal EL2124 4-chn Digital Ouput; Rail: Middle; BoxNextB: LYFCEQDD; BoxPrev: XUXHOGEX; PortPrevFull: 1032/B; PortPrevShort: B; Fullname: TIID^End X (EtherCAT)^EndX Link L0 (EK1501-0010)^EndX Link L6 (EK1521)^EndX Common M0 (EK1100)^EndX Common M8 (EL2124); BoxAddr: 1033; Disabled: False
B646 = TerminalEL2124: EtherCAT Terminal EL2124 4-chn Digital Ouput; Rail: Middle; BoxNextB: XFAMXWBY; BoxPrev: KVUVDLYS; PortPrevFull: 1033/B; PortPrevShort: B; Fullname: TIID^End X (EtherCAT)^EndX Link L0 (EK1501-0010)^EndX Link L6 (EK1521)^EndX Common M0 (EK1100)^EndX Common M9 (EL2124); BoxAddr: 1034; Disabled: False
B647 = TerminalEL2124: EtherCAT Terminal EL2124 4-chn Digital Ouput; Rail: Middle; BoxNextB: DIOBSBLV; BoxPrev: LYFCEQDD; PortPrevFull: 1034/B; PortPrevShort: B; Fullname: TIID^End X (EtherCAT)^EndX Link L0 (EK1501-0010)^EndX Link L6 (EK1521)^EndX Common M0 (EK1100)^EndX Common M10 (EL2124); BoxAddr: 1035; Disabled: False
B648 = TerminalEL2124: EtherCAT Terminal EL2124 4-chn Digital Ouput; Rail: Middle; BoxNextB: YSEKBQNW; BoxPrev: XFAMXWBY; PortPrevFull: 1035/B; PortPrevShort: B; Fullname: TIID^End X (EtherCAT)^EndX Link L0 (EK1501-0010)^EndX Link L6 (EK1521)^EndX Common M0 (EK1100)^EndX Common M11 (EL2124); BoxAddr: 1036; Disabled: False
B649 = TerminalEL2124: EtherCAT Terminal EL2124 4-chn Digital Ouput; Rail: Middle; BoxNextB: JDKDFXHE; BoxPrev: DIOBSBLV; PortPrevFull: 1036/B; PortPrevShort: B; Fullname: TIID^End X (EtherCAT)^EndX Link L0 (EK1501-0010)^EndX Link L6 (EK1521)^EndX Common M0 (EK1100)^EndX Common M12 (EL2124); BoxAddr: 1037; Disabled: False
B650 = TerminalEL2124: EtherCAT Terminal EL2124 4-chn Digital Ouput; Rail: Middle; BoxNextB: ACVGRDSW; BoxPrev: YSEKBQNW; PortPrevFull: 1037/B; PortPrevShort: B; Fullname: TIID^End X (EtherCAT)^EndX Link L0 (EK1501-0010)^EndX Link L6 (EK1521)^EndX Common M0 (EK1100)^EndX Common M13 (EL2124); BoxAddr: 1038; Disabled: False
B651 = TerminalEL9400: EtherCAT Terminal EL9400 Power; BoxType: TerminalPassive; Rail: Middle; BoxNextB: IFMJTOJS; BoxPrev: JDKDFXHE; PortPrevShort: B; Fullname: TIID^End X (EtherCAT)^EndX Link L0 (EK1501-0010)^EndX Link L6 (EK1521)^EndX Common M0 (EK1100)^EndX Common M14 (EL9400); Disabled: False
B652 = TerminalEL2124: EtherCAT Terminal EL2124 4-chn Digital Ouput; Rail: Middle; BoxNextB: OMOWAEKP; BoxPrev: ACVGRDSW; PortPrevFull: 1038/B; PortPrevShort: B; Fullname: TIID^End X (EtherCAT)^EndX Link L0 (EK1501-0010)^EndX Link L6 (EK1521)^EndX Common M0 (EK1100)^EndX Common M15 (EL2124); BoxAddr: 1039; Disabled: False
B653 = TerminalEL2124: EtherCAT Terminal EL2124 4-chn Digital Ouput; Rail: Middle; BoxNextB: DBBNDJTM; BoxPrev: IFMJTOJS; PortPrevFull: 1039/B; PortPrevShort: B; Fullname: TIID^End X (EtherCAT)^EndX Link L0 (EK1501-0010)^EndX Link L6 (EK1521)^EndX Common M0 (EK1100)^EndX Common M16 (EL2124); BoxAddr: 1040; Disabled: False
B654 = TerminalEL2124: EtherCAT Terminal EL2124 4-chn Digital Ouput; Rail: Middle; BoxNextB: LYPJMGVW; BoxPrev: OMOWAEKP; PortPrevFull: 1040/B; PortPrevShort: B; Fullname: TIID^End X (EtherCAT)^EndX Link L0 (EK1501-0010)^EndX Link L6 (EK1521)^EndX Common M0 (EK1100)^EndX Common M17 (EL2124); BoxAddr: 1041; Disabled: False
B655 = TerminalEL2124: EtherCAT Terminal EL2124 4-chn Digital Ouput; Rail: Middle; BoxNextB: QXLUEBBI; BoxPrev: DBBNDJTM; PortPrevFull: 1041/B; PortPrevShort: B; Fullname: TIID^End X (EtherCAT)^EndX Link L0 (EK1501-0010)^EndX Link L6 (EK1521)^EndX Common M0 (EK1100)^EndX Common M18 (EL2124); BoxAddr: 1042; Disabled: False
B656 = TerminalEL2124: EtherCAT Terminal EL2124 4-chn Digital Ouput; Rail: Middle; BoxNextB: IMBLLVPI; BoxPrev: LYPJMGVW; PortPrevFull: 1042/B; PortPrevShort: B; Fullname: TIID^End X (EtherCAT)^EndX Link L0 (EK1501-0010)^EndX Link L6 (EK1521)^EndX Common M0 (EK1100)^EndX Common M19 (EL2124); BoxAddr: 1043; Disabled: False
B657 = CouplerEK1110: EtherCAT Coupler Extension; BoxType: Terminal; Rail: Middle; BoxNextB: ADQIHKND; BoxPrev: QXLUEBBI; PortPrevFull: 1043/B; PortPrevShort: B; Fullname: TIID^End X (EtherCAT)^EndX Link L0 (EK1501-0010)^EndX Link L6 (EK1521)^EndX Common M0 (EK1100)^EndX Common M20 (EK1110); BoxAddr: 1044; Disabled: False
B658 = CouplerEK1100: EtherCAT Coupler; Rail: Right; BoxNextB: IRQQIJXQ; BoxNextC: YKLANJOD; BoxPrev: IMBLLVPI; PortPrevFull: 1044/B; PortPrevShort: B 'X1 OUT'; Fullname: TIID^End X (EtherCAT)^EndX Link L0 (EK1501-0010)^EndX Link L6 (EK1521)^EndX Common R0 (EK1100); BoxPorts: Junction; BoxAddr: 1045; Disabled: False
B659 = TerminalEL3102: EtherCAT Terminal EL3102 2-chn Analog Input; Rail: Right; BoxNextB: AHSJDPSM; BoxPrev: ADQIHKND; PortPrevFull: 1045/B; PortPrevShort: B; Fullname: TIID^End X (EtherCAT)^EndX Link L0 (EK1501-0010)^EndX Link L6 (EK1521)^EndX Common R0 (EK1100)^EndX Common R1 (EL3102); BoxAddr: 1046; Disabled: False
B660 = TerminalEL3102: EtherCAT Terminal EL3102 2-chn Analog Input; Rail: Right; BoxNextB: XEETILBX; BoxPrev: IRQQIJXQ; PortPrevFull: 1046/B; PortPrevShort: B; Fullname: TIID^End X (EtherCAT)^EndX Link L0 (EK1501-0010)^EndX Link L6 (EK1521)^EndX Common R0 (EK1100)^EndX Common R2 (EL3102); BoxAddr: 1047; Disabled: False
B661 = TerminalEL3102: EtherCAT Terminal EL3102 2-chn Analog Input; Rail: Right; BoxNextB: YWGSFPNO; BoxPrev: AHSJDPSM; PortPrevFull: 1047/B; PortPrevShort: B; Fullname: TIID^End X (EtherCAT)^EndX Link L0 (EK1501-0010)^EndX Link L6 (EK1521)^EndX Common R0 (EK1100)^EndX Common R3 (EL3102); BoxAddr: 1048; Disabled: False
B662 = TerminalEL3102: EtherCAT Terminal EL3102 2-chn Analog Input; Rail: Right; BoxNextB: VIWONTUE; BoxPrev: XEETILBX; PortPrevFull: 1048/B; PortPrevShort: B; Fullname: TIID^End X (EtherCAT)^EndX Link L0 (EK1501-0010)^EndX Link L6 (EK1521)^EndX Common R0 (EK1100)^EndX Common R4 (EL3102); BoxAddr: 1049; Disabled: False
B663 = TerminalEL4132: EtherCAT Terminal EL4132 2-chn Analog Ouput; Rail: Right; BoxNextB: YORBHFHE; BoxPrev: YWGSFPNO; PortPrevFull: 1049/B; PortPrevShort: B; Fullname: TIID^End X (EtherCAT)^EndX Link L0 (EK1501-0010)^EndX Link L6 (EK1521)^EndX Common R0 (EK1100)^EndX Common R5 (EL4132); BoxAddr: 1050; Disabled: False
B664 = TerminalEL9400: EtherCAT Terminal EL9400 Power; BoxType: TerminalPassive; Rail: Right; BoxNextB: IPSQPETJ; BoxPrev: VIWONTUE; PortPrevShort: B; Fullname: TIID^End X (EtherCAT)^EndX Link L0 (EK1501-0010)^EndX Link L6 (EK1521)^EndX Common R0 (EK1100)^EndX Common R6 (EL9400); Disabled: False
B665 = TerminalEL1124: EtherCAT Terminal EL1124 4-chn Digital Input; Rail: Right; BoxNextB: FVVFYYLD; BoxPrev: YORBHFHE; PortPrevFull: 1050/B; PortPrevShort: B; Fullname: TIID^End X (EtherCAT)^EndX Link L0 (EK1501-0010)^EndX Link L6 (EK1521)^EndX Common R0 (EK1100)^EndX Common R7 (EL1124); BoxAddr: 1051; Disabled: False
B666 = TerminalEL2124: EtherCAT Terminal EL2124 4-chn Digital Ouput; Rail: Right; BoxNextB: SLMAXYOP; BoxPrev: IPSQPETJ; PortPrevFull: 1051/B; PortPrevShort: B; Fullname: TIID^End X (EtherCAT)^EndX Link L0 (EK1501-0010)^EndX Link L6 (EK1521)^EndX Common R0 (EK1100)^EndX Common R8 (EL2124); BoxAddr: 1052; Disabled: False
B667 = TerminalEL9190: EtherCAT Terminal EL9190 Supply; BoxType: TerminalPassive; Rail: Right; BoxNextB: GIBXLLMK; BoxPrev: FVVFYYLD; PortPrevShort: B; Fullname: TIID^End X (EtherCAT)^EndX Link L0 (EK1501-0010)^EndX Link L6 (EK1521)^EndX Common R0 (EK1100)^EndX Common R9 (EL9190); Disabled: False
B668 = TerminalEL2124: EtherCAT Terminal EL2124 4-chn Digital Ouput; Rail: Right; BoxNextB: CJVAXCQR; BoxPrev: SLMAXYOP; PortPrevFull: 1052/B; PortPrevShort: B; Fullname: TIID^End X (EtherCAT)^EndX Link L0 (EK1501-0010)^EndX Link L6 (EK1521)^EndX Common R0 (EK1100)^EndX Common R10 (EL2124); BoxAddr: 1053; Disabled: False
B669 = TerminalEL2124: EtherCAT Terminal EL2124 4-chn Digital Ouput; Rail: Right; BoxNextB: KWTMOKRK; BoxPrev: GIBXLLMK; PortPrevFull: 1053/B; PortPrevShort: B; Fullname: TIID^End X (EtherCAT)^EndX Link L0 (EK1501-0010)^EndX Link L6 (EK1521)^EndX Common R0 (EK1100)^EndX Common R11 (EL2124); BoxAddr: 1054; Disabled: False
B670 = TerminalEL2124: EtherCAT Terminal EL2124 4-chn Digital Ouput; Rail: Right; BoxNextB: OIGWPELY; BoxPrev: CJVAXCQR; PortPrevFull: 1054/B; PortPrevShort: B; Fullname: TIID^End X (EtherCAT)^EndX Link L0 (EK1501-0010)^EndX Link L6 (EK1521)^EndX Common R0 (EK1100)^EndX Common R12 (EL2124); BoxAddr: 1055; Disabled: False
B671 = TerminalEL2124: EtherCAT Terminal EL2124 4-chn Digital Ouput; Rail: Right; BoxNextB: LSWMPBHA; BoxPrev: KWTMOKRK; PortPrevFull: 1055/B; PortPrevShort: B; Fullname: TIID^End X (EtherCAT)^EndX Link L0 (EK1501-0010)^EndX Link L6 (EK1521)^EndX Common R0 (EK1100)^EndX Common R13 (EL2124); BoxAddr: 1056; Disabled: False
B672 = TerminalEL2124: EtherCAT Terminal EL2124 4-chn Digital Ouput; Rail: Right; BoxNextB: UUVJYVGV; BoxPrev: OIGWPELY; PortPrevFull: 1056/B; PortPrevShort: B; Fullname: TIID^End X (EtherCAT)^EndX Link L0 (EK1501-0010)^EndX Link L6 (EK1521)^EndX Common R0 (EK1100)^EndX Common R14 (EL2124); BoxAddr: 1057; Disabled: False
B673 = TerminalEL9011: EtherCAT Terminal EL9011 End; BoxType: TerminalPassive; Rail: Right; BoxPrev: LSWMPBHA; PortPrevShort: B; Fullname: TIID^End X (EtherCAT)^EndX Link L0 (EK1501-0010)^EndX Link L6 (EK1521)^EndX Common R0 (EK1100)^EndX Common R15 (EL9011); Disabled: False
V451 = LowNoiseVco_LowNoiseVcoInStruct: LowNoiseVcoInStruct; BoxType: Variable; Instance: H1IscEndX Instance; PLC: H1IscEndX; Task: IscEStd
V535 V537 = CommonMode_CommonModeInStruct: CommonModeInStruct; BoxType: Variable; Instance: H1IscEndX Instance; PLC: H1IscEndX; Task: IscEStd
V536 V538 = CommonMode_CommonModeOutStruct: CommonModeOutStruct; BoxType: Variable; Instance: H1IscEndX Instance; PLC: H1IscEndX; Task: IscEStd
V539 = LowNoiseVco_LowNoiseVcoOutStruct: LowNoiseVcoOutStruct; BoxType: Variable; Instance: H1IscEndX Instance; PLC: H1IscEndX; Task: IscEStd
V540 = DelayLogic_DelayLogicOutStruct: DelayLogicOutStruct; BoxType: Variable; Instance: H1IscEndX Instance; PLC: H1IscEndX; Task: IscEStd
V541 = DelayLogic_DelayLogicOutStructB: DelayLogicOutStruct; BoxType: Variable; Instance: H1IscEndX Instance; PLC: H1IscEndX; Task: IscEStd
